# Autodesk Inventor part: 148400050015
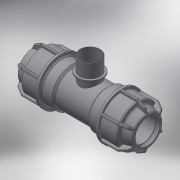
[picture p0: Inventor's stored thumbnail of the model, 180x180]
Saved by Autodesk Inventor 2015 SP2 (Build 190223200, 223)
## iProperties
Created: 2017-08
Part Number: 148400050015
Material: Generic
Description: PLASSON L.14 TEE MALE ADAPTOR (SILVER) 50-1.1/2"-50
Document SubType Name: Modeling
Designer: KIM
Density: 1 g/cm^3
Appearance: Default
Author: KIM
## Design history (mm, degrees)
derived "148400.ipt"
feature "Solid1::148400.ipt"
feature "Solid2::148400.ipt"
tag "TaggingFeature1"
body "Solid1"
body "Solid2"
other parameters: "d2" = 72, "d4" = 15 deg, "d5" = 47.52, "d6" = 15.6816, "d10" = 92, "d16" = 51, "d17" = 3.6, "d24" = 3.6, "d25" = 82.8, "d26" = 69, "d27" = 3.6, "d28" = 135 deg, "d29" = 2.16, "d31" = 2.5, "d46" = 150 deg, "d49" = 4.6, "d50" = 0, "d58" = 1.5, "d61" = 360 deg, "d63" = 45, "d64" = 103.5, "d80" = 72, "d81" = 4, "d84" = 3.6, "d94" = 73, "d96" = 47.803, "d108" = 1.5, "d111" = 0, "d113" = 45, "d114" = 57.3636, "d115" = 22, "d116" = 2.2, "d117" = 47.803, "R_" = 47.803, "E_" = 92, "H_" = 207, "l_" = 72, "l_2" = 22, "A_" = 73
